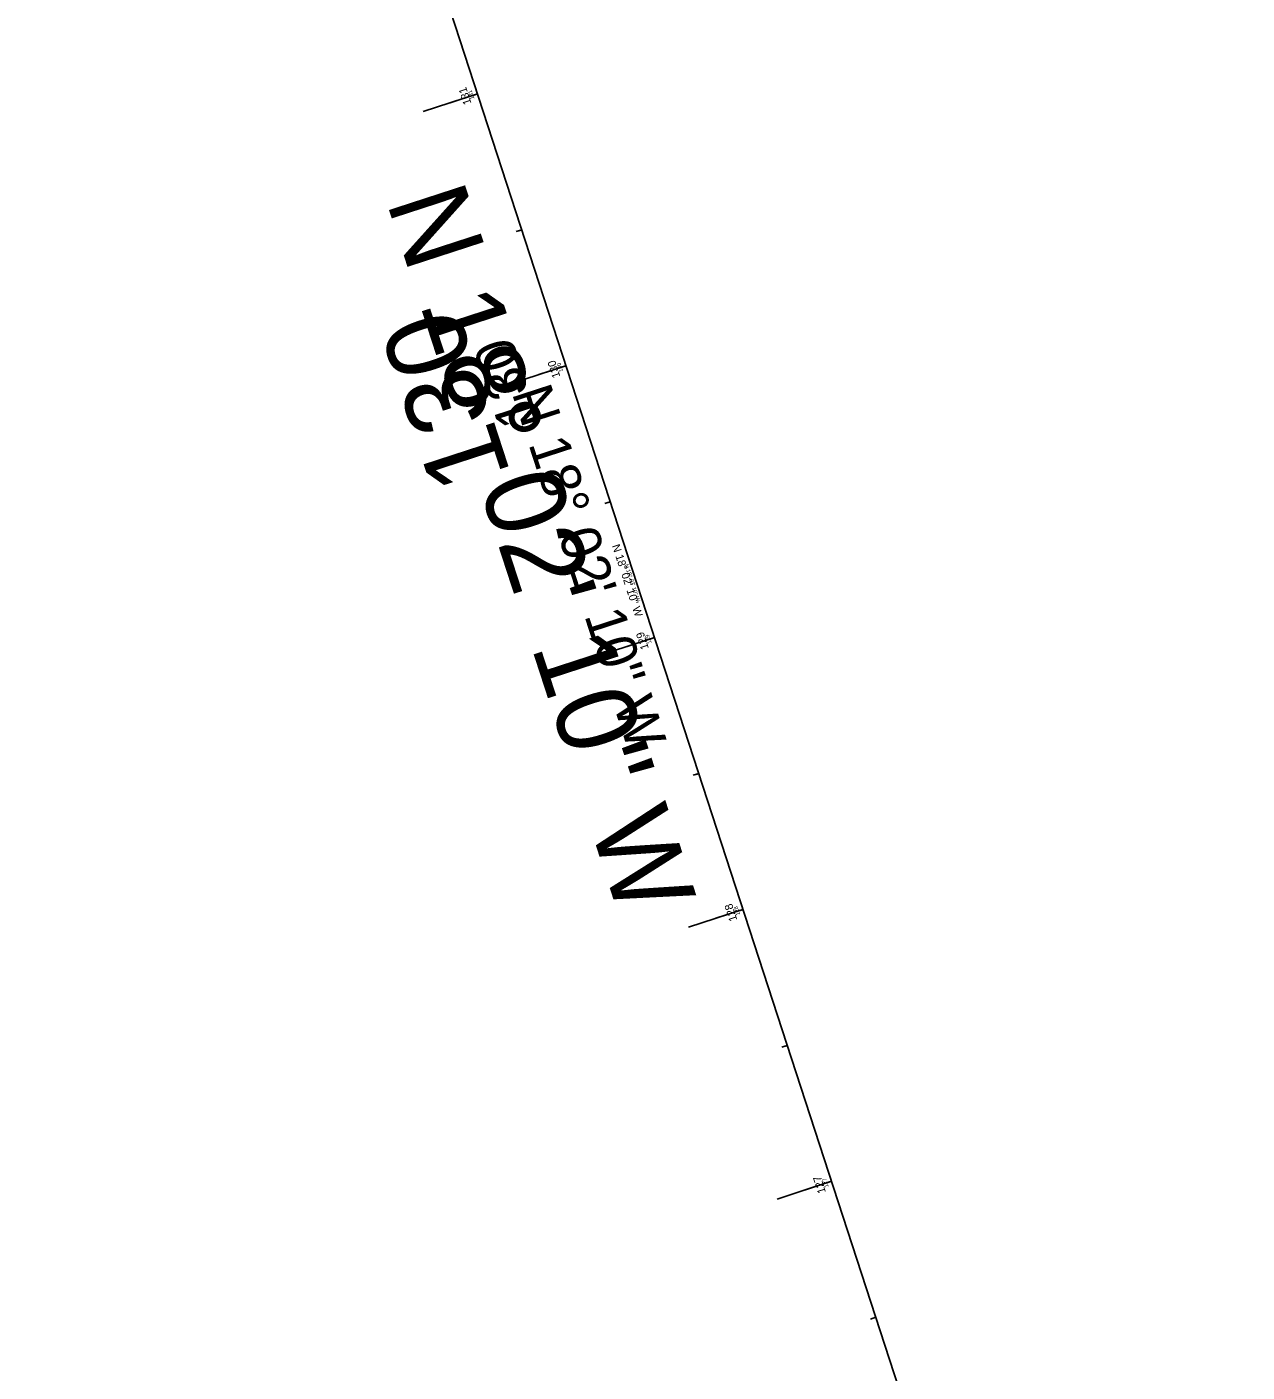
# Model space of a CAD drawing. Extents: x 1794716 to 1797874, y 325521 to 329174.
# Drawn here: x 1795747 to 1796173.8, y 328233.2 to 328703.7 of the extents above; entities that cross this region are included whole.
import ezdxf

# ---------------------------------------------------------------- set-up
doc = ezdxf.new("R2010")
doc.units = 0
for name, color, linetype in [('GE_P_CL_10', 7, 'Continuous'), ('GE_P_CL_100', 7, 'Continuous'), ('GE_P_CL_20', 7, 'Continuous'), ('GE_P_CL_200', 7, 'Continuous'), ('RW_X_CL_20', 7, 'Continuous')]:
    doc.layers.add(name, color=color, linetype=linetype)

msp = doc.modelspace()

# ---------------------------------------------------------------- linework, layer by layer
at = {"layer": 'GE_P_CL_10'}
for p, q in [((1796173.82, 327853.48), (1795747.03, 329164.17)), ((1795904.61, 328680.23), (1795903.66, 328679.92)), ((1795920.09, 328632.69), (1795919.14, 328632.38)), ((1795935.57, 328585.15), (1795934.62, 328584.84)), ((1795951.06, 328537.6), (1795950.1, 328537.29)), ((1795966.54, 328490.06), (1795965.59, 328489.75)), ((1795982.02, 328442.52), (1795981.07, 328442.21)), ((1795997.5, 328394.97), (1795996.55, 328394.66)), ((1796012.98, 328347.43), (1796012.03, 328347.12)), ((1796028.46, 328299.89), (1796027.51, 328299.58)), ((1796043.94, 328252.35), (1796042.99, 328252.04))]:
    msp.add_line(p, q, dxfattribs=at)
at = {"layer": 'GE_P_CL_100'}
for p, q in [((1796173.82, 327853.48), (1795747.03, 329164.17)), ((1795904.61, 328680.23), (1795895.1, 328677.14)), ((1795935.57, 328585.15), (1795926.07, 328582.05)), ((1795966.54, 328490.06), (1795957.03, 328486.96)), ((1795997.5, 328394.97), (1795987.99, 328391.88)), ((1796028.46, 328299.89), (1796018.95, 328296.79))]:
    msp.add_line(p, q, dxfattribs=at)
at = {"layer": 'GE_P_CL_20'}
for p, q in [((1796173.82, 327853.48), (1795747.03, 329164.17)), ((1795904.61, 328680.23), (1795902.71, 328679.61)), ((1795920.09, 328632.69), (1795918.19, 328632.07)), ((1795935.57, 328585.15), (1795933.67, 328584.53)), ((1795951.06, 328537.6), (1795949.15, 328536.98)), ((1795966.54, 328490.06), (1795964.63, 328489.44)), ((1795982.02, 328442.52), (1795980.12, 328441.9)), ((1795997.5, 328394.97), (1795995.6, 328394.36)), ((1796012.98, 328347.43), (1796011.08, 328346.81)), ((1796028.46, 328299.89), (1796026.56, 328299.27)), ((1796043.94, 328252.35), (1796042.04, 328251.73))]:
    msp.add_line(p, q, dxfattribs=at)
at = {"layer": 'GE_P_CL_200'}
for p, q in [((1796173.82, 327853.48), (1795747.03, 329164.17)), ((1795904.61, 328680.23), (1795885.6, 328674.04)), ((1795935.57, 328585.15), (1795916.56, 328578.95)), ((1795966.54, 328490.06), (1795947.52, 328483.87)), ((1795997.5, 328394.97), (1795978.48, 328388.78)), ((1796028.46, 328299.89), (1796009.44, 328293.7))]:
    msp.add_line(p, q, dxfattribs=at)
at = {"layer": 'RW_X_CL_20'}
msp.add_line((1796173.82, 327853.48), (1795747.03, 329164.17), dxfattribs=at)

# ---------------------------------------------------------------- texts
at = {"layer": 'GE_P_CL_10'}
for s, rotation, p in [('131', 108.0361, (1795903.57, 328678.59)), ('130', 108.0361, (1795934.61, 328583.25)), ('N 18%%d 02\' 10" W', 288.0361, (1795956.04, 328515.51)), ('129', 108.0361, (1795965.56, 328488.21)), ('128', 108.0361, (1795996.52, 328393.15)), ('127', 108.0361, (1796027.5, 328298))]:
    msp.add_text(s, height=1.4, rotation=rotation, dxfattribs=at).set_placement(p)
at = {"layer": 'GE_P_CL_100'}
for s, rotation, p in [('130', 108.0361, (1795925.97, 328566.2)), ('N 18%%d 02\' 10" W', 288.0361, (1795916.57, 328575.68))]:
    msp.add_text(s, height=14, rotation=rotation, dxfattribs=at).set_placement(p)
at = {"layer": 'GE_P_CL_20'}
for s, rotation, p in [('131', 108.0361, (1795902.53, 328676.95)), ('130', 108.0361, (1795933.65, 328581.36)), ('N 18%%d 02\' 10" W', 288.0361, (1795951.65, 328522.2)), ('129', 108.0361, (1795964.58, 328486.37)), ('128', 108.0361, (1795995.53, 328391.32)), ('127', 108.0361, (1796026.53, 328296.12))]:
    msp.add_text(s, height=2.8, rotation=rotation, dxfattribs=at).set_placement(p)
at = {"layer": 'GE_P_CL_200'}
for s, rotation, p in [('N 18%%d 02\' 10" W', 288.0361, (1795872.72, 328642.54)), ('130', 108.0361, (1795916.36, 328547.25))]:
    msp.add_text(s, height=28, rotation=rotation, dxfattribs=at).set_placement(p)

doc.saveas('drawing.dxf')
